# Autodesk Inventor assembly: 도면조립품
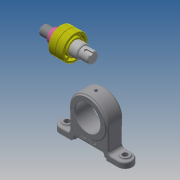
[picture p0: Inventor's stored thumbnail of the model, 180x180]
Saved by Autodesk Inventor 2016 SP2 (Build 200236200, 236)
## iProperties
Created: 2019-05
Part Number: 도면조립품
Document SubType Name: Assembly
Designer: EZ
Author: EZ
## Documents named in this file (5)
- Y:\490504V1044 이택근\도면조립품.iam
- Y:\490504V1044 이택근\본체.ipt
- Y:\490504V1044 이택근\앵귤러 볼 베어링 7205.ipt
- Y:\490504V1044 이택근\축.ipt
- Y:\490504V1044 이택근\칼라.ipt
